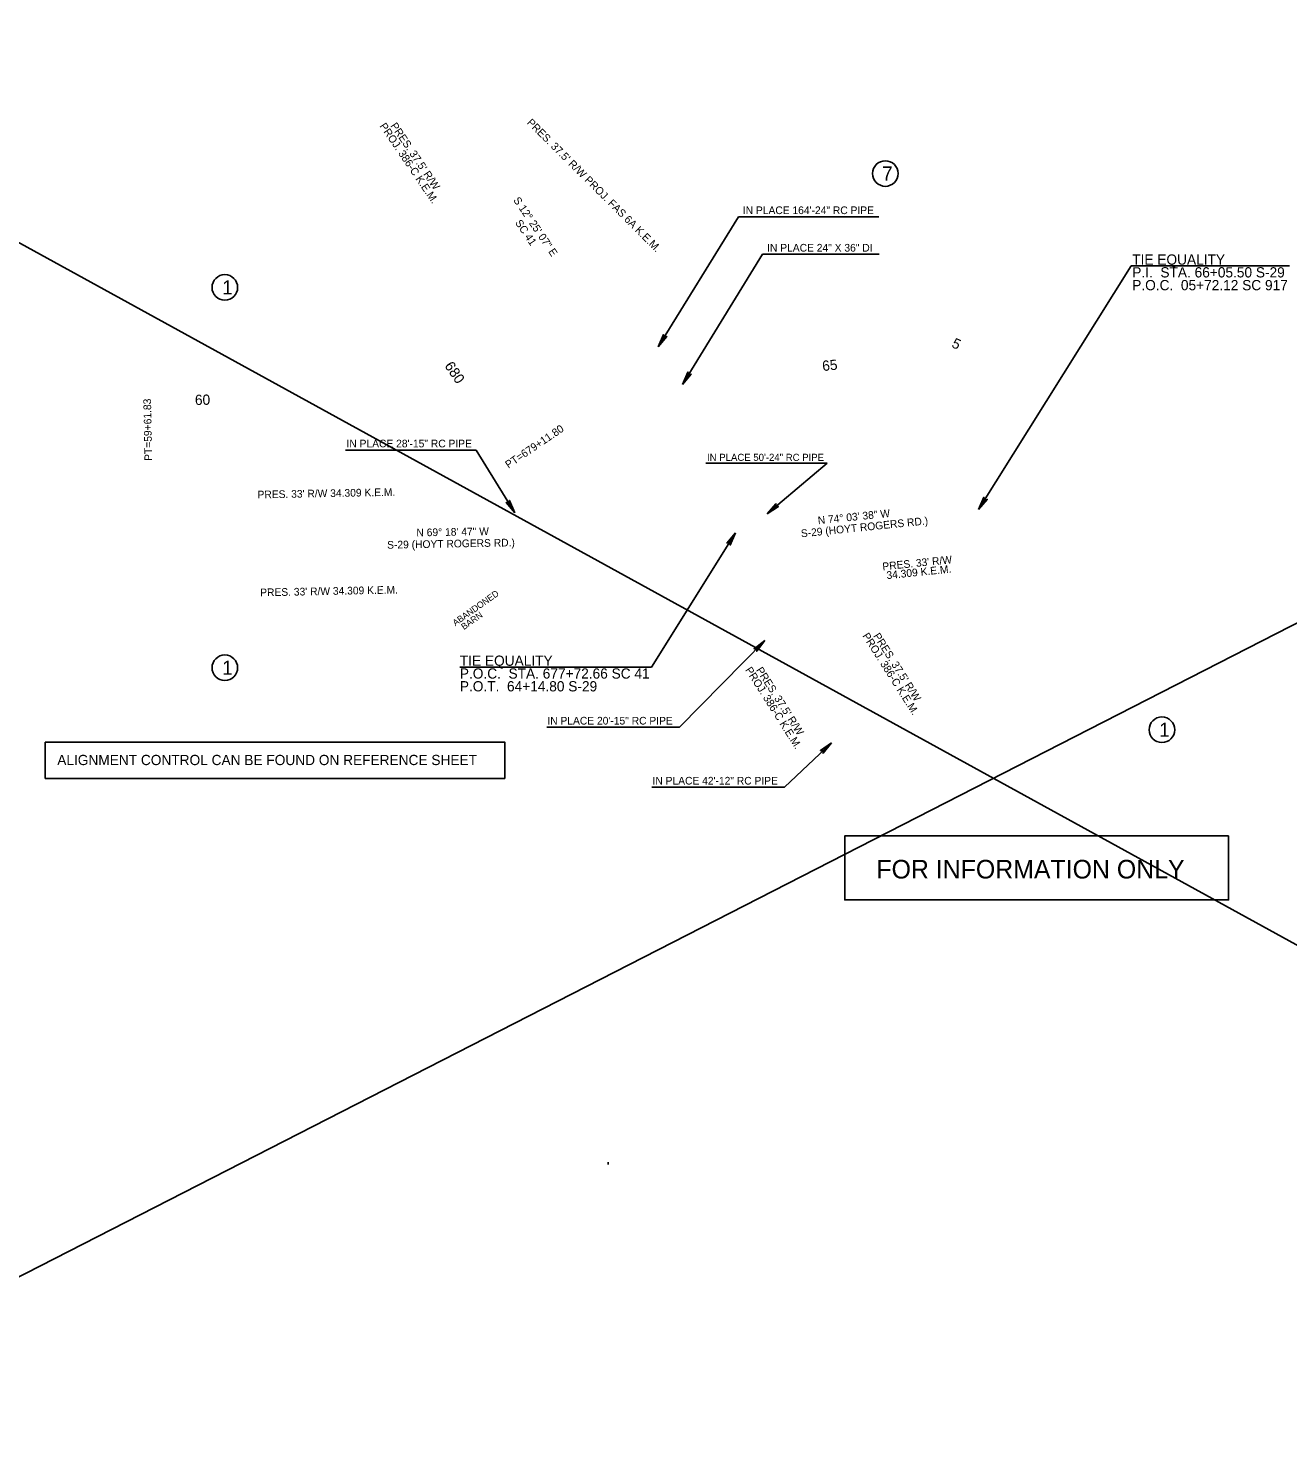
# Model space of a CAD drawing. Extents: x 2522404 to 2525275, y 885432 to 893540.
# Drawn here: x 2523374 to 2524359, y 891287 to 892393 of the extents above; entities that cross this region are included whole.
import ezdxf

# ---------------------------------------------------------------- set-up
doc = ezdxf.new("R2010")
doc.units = 0
for name, color, linetype in [('Default', 7, 'Continuous'), ('RD_DDB_ElevTX', 7, 'Continuous'), ('RD_DDB_Profile_EX', 7, 'Continuous'), ('RD_DDB_Profile_Lbl', 7, 'Continuous'), ('RD_DDB_Profile_PR', 7, 'Continuous'), ('RD_EX_Misc', 7, 'Continuous'), ('RD_HC_Cl', 7, 'Continuous'), ('RD_HC_Data_Tic', 7, 'Continuous'), ('RD_HY_TX1', 7, 'Continuous'), ('RD_PD_Final_LnLine', 7, 'Continuous'), ('RD_PD_RW_TX', 7, 'Continuous'), ('RD_SHT_IplotShp', 7, 'Continuous'), ('RD_TX_Profile', 7, 'Continuous')]:
    doc.layers.add(name, color=color, linetype=linetype)

# ---------------------------------------------------------------- blocks, each defined once
blk = doc.blocks.new('ah_')
at = {"layer": 'Default'}
blk.add_lwpolyline([(0, 0), (-1.4, -10.4), (0, -8.8), (1.5, -10.4)], close=True, dxfattribs=at)
blk = doc.blocks.new('ah4')
at = {"layer": 'Default', "rotation": -90.00000000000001}
blk.add_blockref('ah_', (0, 0), dxfattribs=at)
blk = doc.blocks.new('AH4_')
at = {"layer": 'Default'}
blk.add_lwpolyline([(0, 0), (-10.4, 1.5), (-8.8, 0), (-10.4, -1.5)], close=True, dxfattribs=at)

msp = doc.modelspace()

# ---------------------------------------------------------------- linework, layer by layer
at = {"layer": 'Default'}
msp.add_line((2523827.6, 891505.2), (2523827.6, 891507), dxfattribs=at)
at = {"layer": 'RD_DDB_ElevTX'}
for p, q in [((2523122.7, 891292.5), (2525274.9, 892393.1)), ((2523105.6, 892369.2), (2525153.6, 891243.7))]:
    msp.add_line(p, q, dxfattribs=at)
at = {"layer": 'RD_DDB_Profile_PR'}
msp.add_lwpolyline([(2523387.6, 891835.3), (2523387.6, 891806.9), (2523746.8, 891806.9), (2523746.8, 891835.3)], close=True, dxfattribs=at)
at = {"layer": 'RD_EX_Misc'}
for centre in [(2524044.3, 892279.6), (2523528, 892190.6), (2523528, 891893.4), (2524260.5, 891844.9)]:
    msp.add_circle(centre, 10, dxfattribs=at)
at = {"layer": 'RD_HY_TX1'}
for p, q in [((2523951.8, 892013.7), (2523998.8, 892053.2)), ((2523950, 891914.7), (2523883.5, 891847)), ((2524002.1, 891834.8), (2523965.6, 891800))]:
    msp.add_line(p, q, dxfattribs=at)
for points in [[(2523866.7, 892144.2), (2523929.4, 892245.8)], [(2524039.3, 892245.8), (2523929.4, 892245.8)], [(2523885.7, 892114.8), (2523948.4, 892216.5)], [(2524039.5, 892216.5), (2523948.4, 892216.5)], [(2523724.4, 892063.5), (2523622.4, 892063.5)], [(2523754.6, 892014.5), (2523724.4, 892063.5)], [(2523998.8, 892053.2), (2523903.9, 892053.2)], [(2523883.5, 891847), (2523779.6, 891847)], [(2523965.6, 891800), (2523861.7, 891800)]]:
    msp.add_lwpolyline(points, dxfattribs=at)
at = {"layer": 'RD_PD_RW_TX'}
for p, q in [((2524117.1, 892017), (2524236.4, 892207.5)), ((2524236.4, 892207.5), (2524360.3, 892207.5)), ((2523861.6, 891893.9), (2523927.3, 891998.8)), ((2523711.7, 891893.9), (2523861.6, 891893.9))]:
    msp.add_line(p, q, dxfattribs=at)
at = {"layer": 'RD_TX_Profile'}
msp.add_lwpolyline([(2524312.6, 891761.9), (2524012.6, 891761.9), (2524012.6, 891711.9), (2524312.6, 891711.9)], close=True, dxfattribs=at)

# ---------------------------------------------------------------- block references
at = {"layer": 'RD_HY_TX1'}
for p, yscale, rotation in [((2523866.7, 892144.2), -0.9999999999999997, -121.34907771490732), ((2523885.7, 892114.8), -0.9999999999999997, -121.34907771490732), ((2523951.8, 892013.7), -1, -139.66675838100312), ((2523950, 891914.7), -0.9999999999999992, 45.78486527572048), ((2524002.1, 891834.8), -0.9999999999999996, 43.87905069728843)]:
    msp.add_blockref('ah4', p, dxfattribs=dict(at, yscale=yscale, rotation=rotation))
at = {"layer": 'RD_HY_TX1', "rotation": -58.65092228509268}
msp.add_blockref('ah4', (2523754.6, 892014.5), dxfattribs=at)
at = {"layer": 'RD_PD_Final_LnLine'}
for p, rotation in [((2524117.1, 892017), -122.32812440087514), ((2523927.3, 891998.8), 57.6718755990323)]:
    msp.add_blockref('AH4_', p, dxfattribs=dict(at, rotation=rotation))

# ---------------------------------------------------------------- texts
at = {"layer": 'Default'}
msp.add_text('FOR INFORMATION ONLY', height=14.542, dxfattribs=at).set_placement((2524037.3, 891728.7))
at = {"layer": 'RD_DDB_Profile_EX'}
for s, rotation, p in [('5', 334.2028, (2524095.5, 892144.3)), ('65', 5.8447, (2523995.4, 892125.2)), ('680', 304.2027, (2523699.4, 892129.3)), ('60', 1.0974, (2523504.7, 892098.7))]:
    msp.add_text(s, height=8, rotation=rotation, dxfattribs=at).set_placement(p)
at = {"layer": 'RD_DDB_Profile_Lbl'}
for s, p in [('7', (2524041.8, 892274.1)), ('1', (2523525.9, 892185.1)), ('1', (2523525.9, 891887.9)), ('1', (2524258.3, 891839.4))]:
    msp.add_text(s, height=11, dxfattribs=at).set_placement(p)
at = {"layer": 'RD_DDB_Profile_PR'}
msp.add_text('ALIGNMENT CONTROL CAN BE FOUND ON REFERENCE SHEET', height=8, dxfattribs=at).set_placement((2523397, 891817.3))
at = {"layer": 'RD_HC_Cl'}
for s, height, rotation, p in [('S 12%%d 25\' 07" E', 6, 304.2027, (2523753.2, 892258.8)), ('SC 41', 6, 304.2027, (2523754.6, 892241.1)), ('TIE EQUALITY', 8, 360, (2524237.3, 892208.4)), ('P.I.  STA. 66+05.50 S-29', 8, 360, (2524237.3, 892198.4)), ('P.O.C.  05+72.12 SC 917', 8, 360, (2524237.3, 892188.4)), ('PT=59+61.83', 6, 91.0974, (2523471.2, 892055.1)), ('PT=679+11.80', 6, 34.2027, (2523749.7, 892048.9)), ('S-29 (HOYT ROGERS RD.)', 6, 5.8447, (2523978.6, 891995.3)), ('N 74%%d 03\' 38" W', 6, 5.8447, (2523991.8, 892005.5)), ('N 69%%d 18\' 47" W', 6, 1.0974, (2523677.8, 891996)), ('S-29 (HOYT ROGERS RD.)', 6, 1.0974, (2523654.9, 891986.4)), ('TIE EQUALITY', 8, 360, (2523711.7, 891894.9)), ('P.O.C.  STA. 677+72.66 SC 41', 8, 360, (2523711.7, 891884.9)), ('P.O.T.  64+14.80 S-29', 8, 360, (2523711.7, 891874.9))]:
    msp.add_text(s, height=height, rotation=rotation, dxfattribs=at).set_placement(p)
at = {"layer": 'RD_HC_Data_Tic'}
for s, p in [('ABANDONED', (2523708.2, 891925.8)), ('  BARN', (2523711.9, 891920.6))]:
    msp.add_text(s, height=5, rotation=35.3647, dxfattribs=at).set_placement(p)
at = {"layer": 'RD_HY_TX1'}
for s, height, p in [('IN PLACE 164\'-24" RC PIPE', 6, (2523932.9, 892247.9)), ('IN PLACE 24" X 36" DI', 6, (2523951.9, 892218.6)), ('IN PLACE 28\'-15" RC PIPE', 6, (2523623.1, 892065.6)), ('IN PLACE 50\'-24" RC PIPE', 5.6, (2523904.9, 892055)), ('IN PLACE 20\'-15" RC PIPE', 6, (2523780.1, 891849)), ('IN PLACE 42\'-12" RC PIPE', 6, (2523862.3, 891802.1))]:
    msp.add_text(s, height=height, dxfattribs=at).set_placement(p)
at = {"layer": 'RD_SHT_IplotShp'}
for s, rotation, p in [("PRES. 37.5' R/W PROJ. FAS 6A K.E.M.", 315.1125, (2523763.7, 892318.9)), ('PROJ. 386-C K.E.M.', 304.2027, (2523648.7, 892316.7)), ("PRES. 37.5' R/W", 304.2027, (2523657.2, 892316.9)), ("PRES. 33' R/W 34.309 K.E.M.", 1.0974, (2523553.6, 892025.7)), ("PRES. 33' R/W", 5.8447, (2524042.3, 891969.5)), ('34.309 K.E.M.', 5.8447, (2524045.5, 891962.6)), ("PRES. 33' R/W 34.309 K.E.M.", 1.1773, (2523555.7, 891949.2)), ('PROJ. 386-C K.E.M.', 302.4758, (2524026.1, 891918.3)), ("PRES. 37.5' R/W", 302.4758, (2524034.6, 891918.2)), ('PROJ. 386-C K.E.M.', 302.4758, (2523934.5, 891891.7)), ("PRES. 37.5' R/W", 302.4758, (2523943, 891891.6))]:
    msp.add_text(s, height=6, rotation=rotation, dxfattribs=at).set_placement(p)

doc.saveas('drawing.dxf')
